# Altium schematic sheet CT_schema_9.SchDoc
size 382 x 278 mm
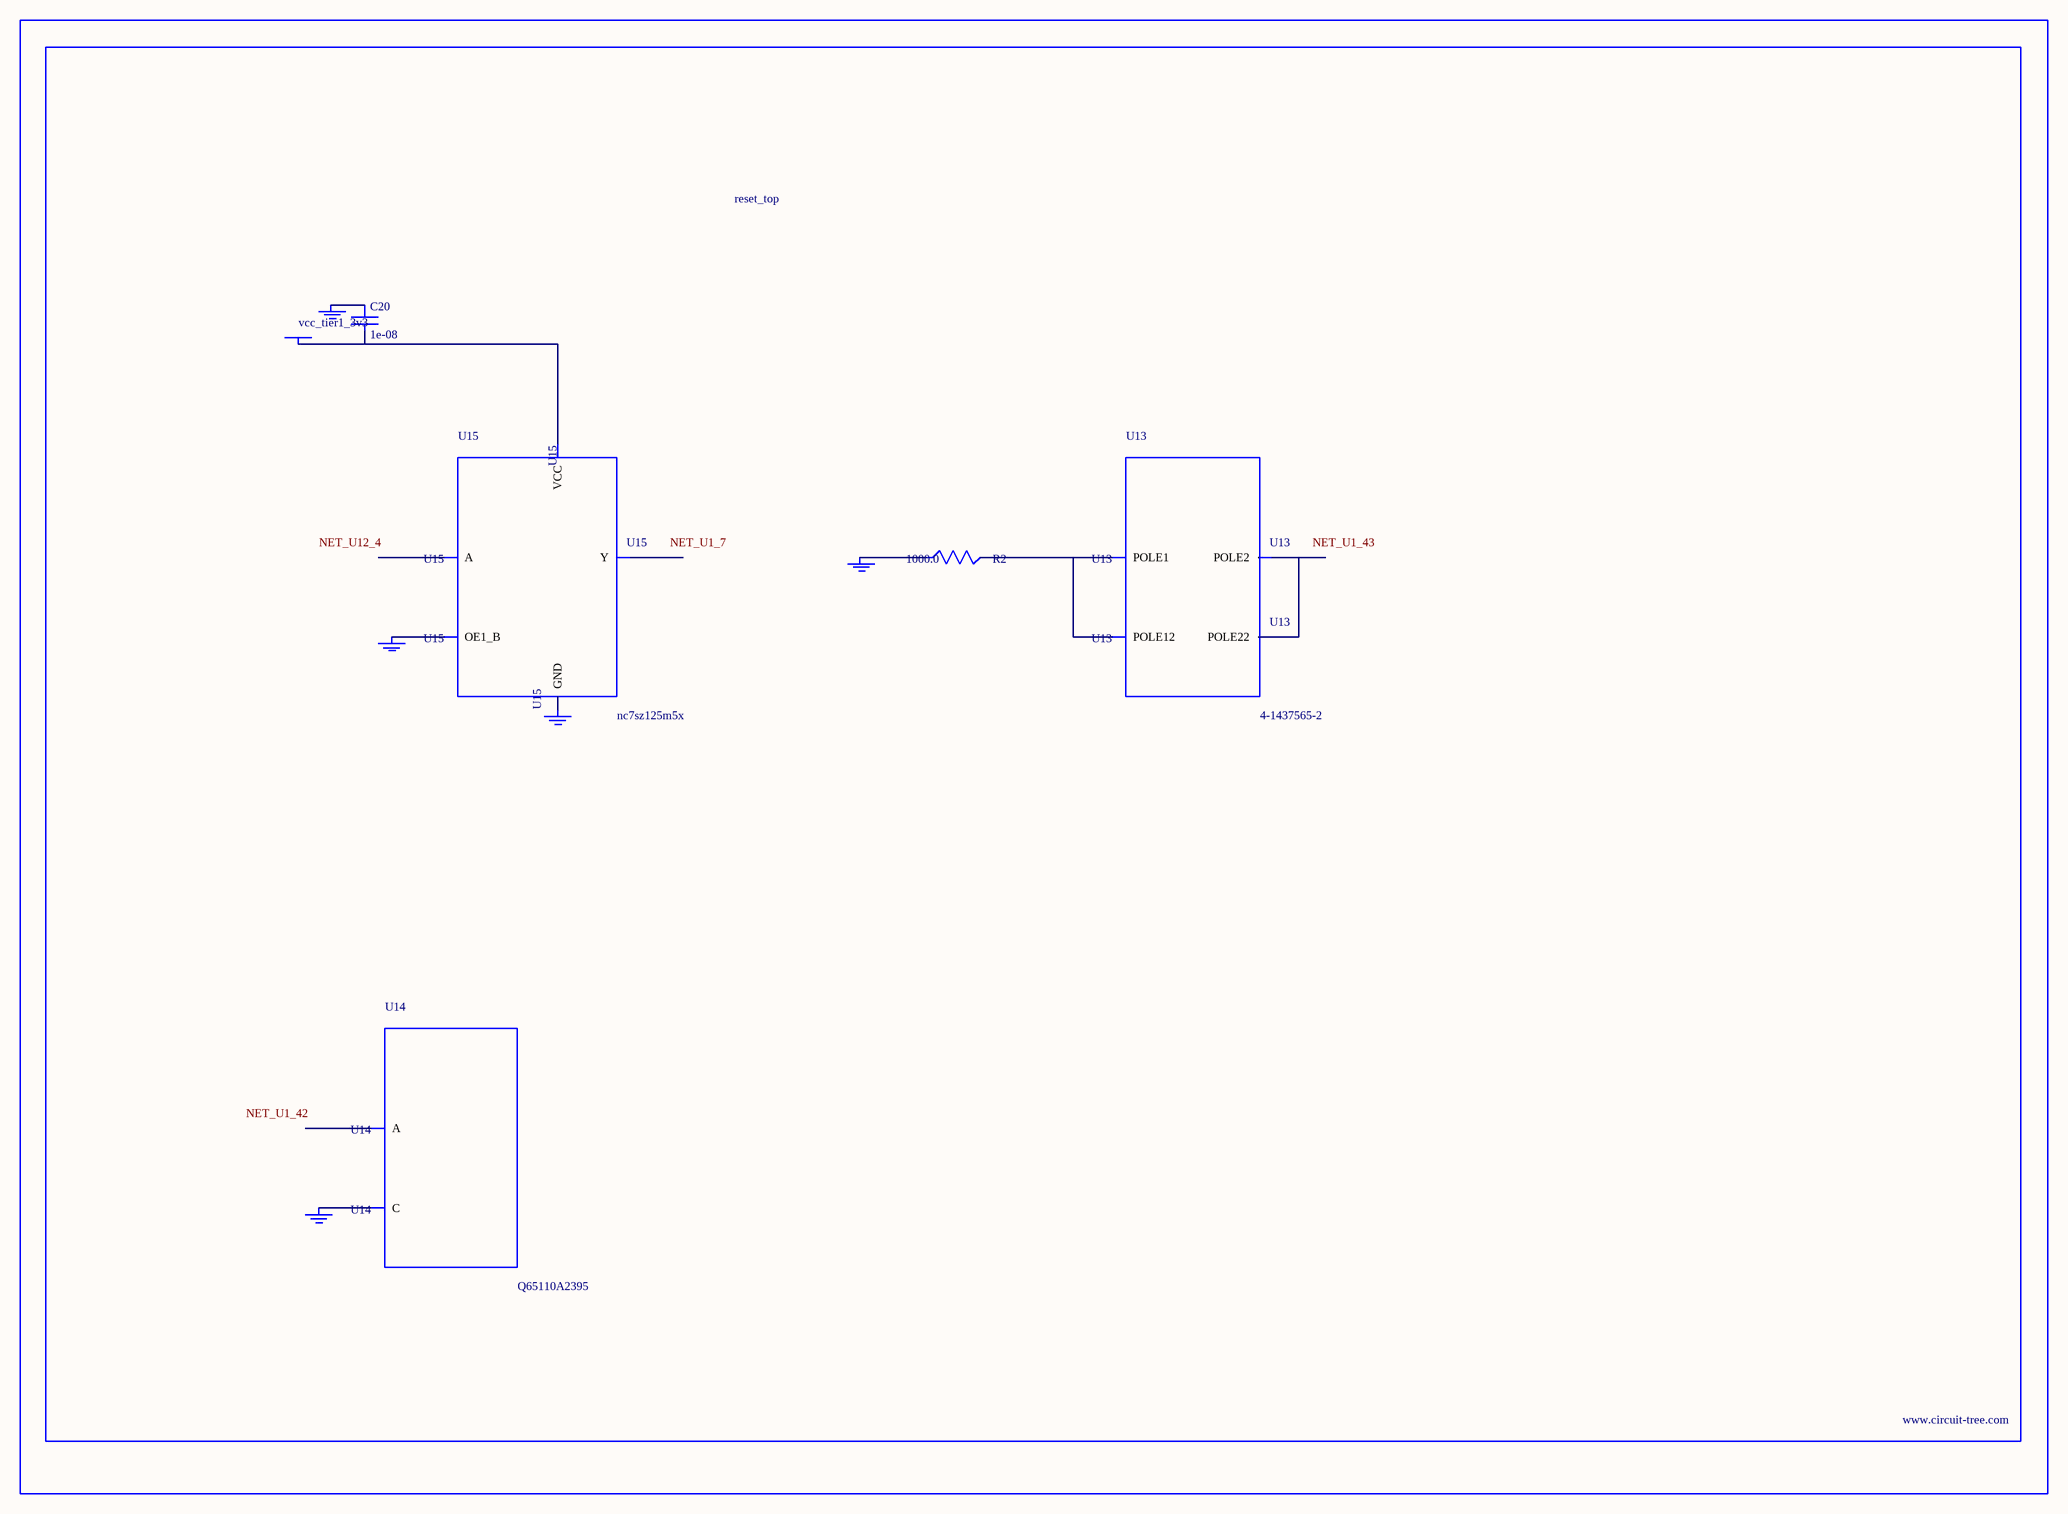
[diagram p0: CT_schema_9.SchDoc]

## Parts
BORDER8  (no value)
C20  1e-08  [C0402]
GND_INSTANCE_8_0  (no value)
GND_INSTANCE_8_1  (no value)
GND_INSTANCE_8_2  (no value)
GND_INSTANCE_8_3  (no value)
GND_INSTANCE_8_4  (no value)
POWER_INSTANCE_8_0  vcc_tier1_3v3
R2  1000.0  [R0603]
U13  4-1437565-2  [SW_4-1437565-2]
U14  Q65110A2395  [LGM67K-G1J2-24-Z]
U15  nc7sz125m5x  [NC7SZ125M5X]

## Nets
NetC20_1: C20.1 GND_INSTANCE_8_2.0(GND)
NetC20_2: C20.2 POWER_INSTANCE_8_0.0(PWR) U15.5(VCC)
NetGND_INSTANCE_8_0_0: GND_INSTANCE_8_0.0(GND) R2.1
NetGND_INSTANCE_8_1_0: GND_INSTANCE_8_1.0(GND) U14.C
NetGND_INSTANCE_8_3_0: GND_INSTANCE_8_3.0(GND) U15.1(OE1_B)
NetGND_INSTANCE_8_4_0: GND_INSTANCE_8_4.0(GND) U15.3(GND)
NetR2_2: R2.2 U13.1(POLE1) U13.2(POLE12)
NetU13_3: U13.3(POLE2) U13.4(POLE22)

Not connected (* = marked no-connect by the designer): U14 A; U15 2(A) 4(Y)

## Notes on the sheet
- Labels drawn without touching a wire or pin: NET_U1_7, NET_U1_42, NET_U1_43, NET_U12_4

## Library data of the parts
BORDER8 = BORDER_PAGE8
C20 = C0402C103K3RAC
GND_INSTANCE_8_0-GND_INSTANCE_8_4 = GND
POWER_INSTANCE_8_0 = PWR
R2 = RC0603JR-071KL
